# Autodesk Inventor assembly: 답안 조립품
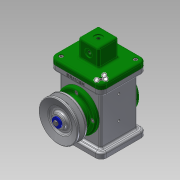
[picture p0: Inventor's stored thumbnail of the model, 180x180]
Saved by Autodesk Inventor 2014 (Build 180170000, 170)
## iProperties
Created: 2017-08
Part Number: 답안 조립품
Document SubType Name: Weldment
Designer: user
Weld Material: Welded Aluminum-6061
Author: user
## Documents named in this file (18)
- C:\Users\user\Desktop\470808V1015\답안 조립품.iam
- C:\Users\user\Desktop\470808V1015\본체.ipt
- C:\Users\user\Desktop\470808V1015\베어링 17 x 40 x 12.ipt
- C:\Users\user\Desktop\470808V1015\볼트 M4 x 8.ipt
- C:\Users\user\Desktop\470808V1015\볼트 M4 x 10.ipt
- C:\Users\user\Desktop\470808V1015\슬라이더.ipt
- C:\Users\user\Desktop\470808V1015\앞커버.ipt
- C:\Users\user\Desktop\470808V1015\오일 실 17 30 8.ipt
- C:\Users\user\Desktop\470808V1015\와셔 4x16.ipt
- C:\Users\user\Desktop\470808V1015\클레비스 핀 6 x 22.ipt
- 클레비스 핀 6 x 22.ipt
- C:\Users\user\Desktop\470808V1015\키 4 x 4 x 12.ipt
- C:\Users\user\Desktop\470808V1015\편심축.ipt
- C:\Users\user\Desktop\470808V1015\E-링.ipt
- C:\Users\user\Desktop\470808V1015\V-벨트풀리.ipt
- C:\Users\user\Desktop\470808V1015\덮개.ipt
- C:\Users\user\Desktop\470808V1015\뒤커버.ipt
- C:\Users\user\Desktop\470808V1015\링크.ipt
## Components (2 placed, 2 different names)
1. E-링:1
2. V-벨트풀리:1
